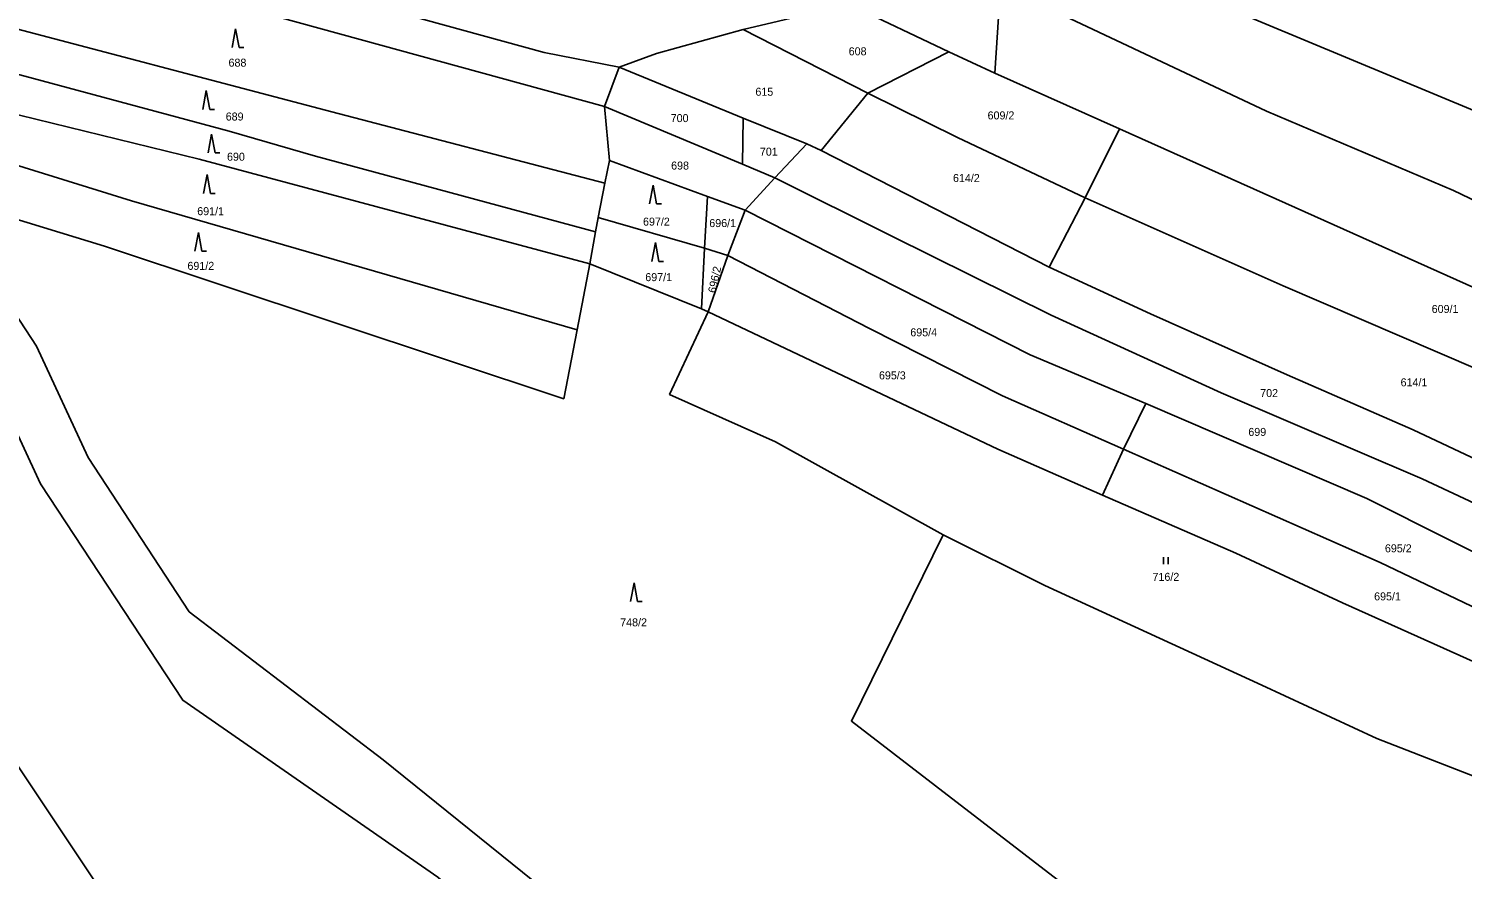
# Model space of a CAD drawing. Extents: x -7483133 to -743907, y -11317770 to -1129777.
# Drawn here: x -748843.6 to -748539, y -1131175.9 to -1130997.2 of the extents above; entities that cross this region are included whole.
import ezdxf

# ---------------------------------------------------------------- set-up
doc = ezdxf.new("R2010")
doc.units = 0
for name, color, linetype in [('Hranice parcel', 7, 'Continuous'), ('Parcelní čísla', 7, 'Continuous'), ('Značky kultur', 7, 'Continuous')]:
    doc.layers.add(name, color=color, linetype=linetype)

msp = doc.modelspace()

# ---------------------------------------------------------------- linework, layer by layer
at = {"layer": 'Hranice parcel'}
for p, q in [((-748638.28, -1131006.71), (-748637.1, -1130988.07)), ((-748669.28, -1130992.07), (-748691.81, -1130997.44)), ((-748669.28, -1130992.07), (-748648.09, -1131002.15)), ((-748691.81, -1130997.44), (-748665.29, -1131010.97)), ((-748665.29, -1131010.97), (-748648.09, -1131002.15)), ((-748648.09, -1131002.15), (-748638.28, -1131006.71)), ((-748721.27, -1131013.77), (-748718.11, -1131005.41)), ((-748718.11, -1131005.41), (-748691.78, -1131016.23)), ((-748638.28, -1131006.71), (-748611.82, -1131018.52)), ((-748665.29, -1131010.97), (-748675.21, -1131023.11)), ((-748691.89, -1131026.01), (-748721.27, -1131013.77)), ((-748720.21, -1131025.25), (-748721.27, -1131013.77)), ((-748691.89, -1131026.01), (-748691.78, -1131016.23)), ((-748691.78, -1131016.23), (-748678.26, -1131021.72)), ((-748611.82, -1131018.52), (-748619.14, -1131033.17)), ((-748685.08, -1131028.93), (-748678.26, -1131021.72)), ((-748678.26, -1131021.72), (-748675.21, -1131023.11)), ((-748675.21, -1131023.11), (-748626.79, -1131047.92)), ((-748721.16, -1131030.03), (-748720.21, -1131025.25)), ((-748699.34, -1131032.91), (-748720.21, -1131025.25)), ((-748685.08, -1131028.93), (-748691.89, -1131026.01)), ((-748722.61, -1131037.34), (-748721.16, -1131030.03)), ((-748691.34, -1131035.8), (-748685.08, -1131028.93)), ((-748699.34, -1131032.91), (-748700.01, -1131043.9)), ((-748691.34, -1131035.8), (-748699.34, -1131032.91)), ((-748619.14, -1131033.17), (-748626.79, -1131047.92)), ((-748691.34, -1131035.8), (-748695.07, -1131045.45)), ((-748723.16, -1131040.37), (-748722.61, -1131037.34)), ((-748700.01, -1131043.9), (-748722.61, -1131037.34)), ((-748724.39, -1131047.18), (-748723.16, -1131040.37)), ((-748700.01, -1131043.9), (-748700.66, -1131056.76)), ((-748700.01, -1131043.9), (-748695.07, -1131045.45)), ((-748695.07, -1131045.45), (-748699.23, -1131057.41)), ((-748724.39, -1131047.18), (-748727.08, -1131061.25)), ((-748700.66, -1131056.76), (-748724.39, -1131047.18)), ((-748699.23, -1131057.41), (-748700.66, -1131056.76)), ((-748606.26, -1131076.91), (-748610.96, -1131086.6)), ((-748610.96, -1131086.6), (-748615.45, -1131096.38))]:
    msp.add_line(p, q, dxfattribs=at)
for points in [[(-748718.11, -1131005.41), (-748734.03, -1131002.28), (-748798.34, -1130984.6), (-748831.06, -1130975.19), (-748876.9, -1130971.17)], [(-748876.9, -1130971.17), (-748808.26, -1130989.85), (-748721.27, -1131013.77)], [(-748433.86, -1131062.5), (-748469.72, -1131045.54), (-748503.59, -1131029.98), (-748535.57, -1131015.06), (-748590.35, -1130992.22), (-748617.7, -1130976.74)], [(-748883.92, -1130988.13), (-748855.69, -1130994.76), (-748779.2, -1131014.91), (-748721.16, -1131030.03)], [(-748637.1, -1130988.07), (-748580.62, -1131014.77), (-748540.84, -1131031.61), (-748501.83, -1131050.32), (-748475.33, -1131062.6), (-748443.88, -1131076.03)], [(-748887.11, -1130995.84), (-748800.99, -1131019), (-748782.66, -1131024.35), (-748723.16, -1131040.37)], [(-748691.81, -1130997.44), (-748710.23, -1131002.5), (-748718.11, -1131005.41)], [(-748890.71, -1131004.53), (-748807.39, -1131024.98), (-748724.39, -1131047.18)], [(-748665.29, -1131010.97), (-748646.27, -1131020.35), (-748619.14, -1131033.17)], [(-748887.67, -1131014.39), (-748859.22, -1131022.19), (-748821.78, -1131033.78), (-748727.08, -1131061.25)], [(-748611.82, -1131018.52), (-748576.55, -1131034.33), (-748532.02, -1131054.31), (-748497.74, -1131070.23), (-748452.21, -1131091.2)], [(-748392.16, -1131506.55), (-748408.97, -1131492.45), (-748455.93, -1131466.65), (-748484.5, -1131445.39), (-748502.39, -1131429.25), (-748511.24, -1131427.32), (-748518.9, -1131418.34), (-748522.93, -1131412.38), (-748534.82, -1131400.07), (-748560.04, -1131371.4), (-748567.63, -1131359.17), (-748618.14, -1131307.59), (-748670.88, -1131247.89), (-748697.81, -1131219.81), (-748711.66, -1131216.37), (-748756.69, -1131177.5), (-748810.83, -1131139.93), (-748841.05, -1131093.93), (-748849.27, -1131076.16), (-748875.35, -1131042.49), (-748884.41, -1131032.45), (-748897.97, -1131021.96), (-748903.36, -1131031.29)], [(-748474.34, -1131130), (-748517.39, -1131106.95), (-748547.53, -1131092.9), (-748590.2, -1131074.61), (-748626.34, -1131058.09), (-748660.21, -1131041.32), (-748685.08, -1131028.93)], [(-748903.36, -1131031.29), (-748905.89, -1131053.47), (-748901.45, -1131069.76), (-748894.6, -1131097.89), (-748881.04, -1131121.08), (-748873.58, -1131134.34), (-748846.57, -1131152.8), (-748823.65, -1131187.26), (-748755.15, -1131237.08), (-748782.58, -1131345.17), (-748793.36, -1131398.73), (-748812.12, -1131488.8), (-748821.02, -1131580.29), (-748829.28, -1131664.88)], [(-748727.08, -1131061.25), (-748729.9, -1131075.88), (-748827.51, -1131043.45), (-748862.93, -1131032.61)], [(-748862.93, -1131032.61), (-748841.96, -1131064.7), (-748830.94, -1131088.32), (-748809.47, -1131121.13), (-748768.27, -1131152.58), (-748729.51, -1131183.85), (-748683.15, -1131218.97), (-748628.13, -1131281.36), (-748623.2, -1131281.94), (-748602.24, -1131308.39), (-748580.92, -1131332.73), (-748557.75, -1131353.82), (-748544.86, -1131363.16), (-748538.91, -1131375.03), (-748525.17, -1131390.76), (-748504.57, -1131408.29), (-748496.26, -1131416.91), (-748493.37, -1131423.24), (-748472.53, -1131441.85), (-748441.17, -1131464.36)], [(-748619.14, -1131033.17), (-748577.08, -1131051.86), (-748535.69, -1131069.64), (-748460.58, -1131106.38)], [(-748606.26, -1131076.91), (-748630.79, -1131066.52), (-748691.34, -1131035.8)], [(-748610.96, -1131086.6), (-748636.68, -1131075.28), (-748664.94, -1131060.97), (-748695.07, -1131045.45)], [(-748626.79, -1131047.92), (-748605.21, -1131057.83), (-748576.19, -1131070.76), (-748549.44, -1131082.45), (-748510.22, -1131100.96), (-748469.85, -1131122.34)], [(-748699.23, -1131057.41), (-748707.43, -1131074.93), (-748684.92, -1131085.04), (-748649.3, -1131104.79)], [(-748615.45, -1131096.38), (-748637.66, -1131086.57), (-748699.23, -1131057.41)], [(-748484.95, -1131136.78), (-748524.02, -1131114.8), (-748559.26, -1131097.09), (-748606.26, -1131076.91)], [(-748489.31, -1131143.89), (-748527.26, -1131124.6), (-748556.46, -1131110.63), (-748610.96, -1131086.6)], [(-748502.01, -1131149.16), (-748525.66, -1131136.67), (-748564.41, -1131119.26), (-748587.13, -1131108.7), (-748615.45, -1131096.38)], [(-748441.17, -1131464.36), (-748441.27, -1131454.86), (-748468.06, -1131411.28), (-748480.68, -1131390.05), (-748513.08, -1131337.18), (-748535.65, -1131293.82), (-748524.03, -1131286.83), (-748537.13, -1131261.56), (-748549.98, -1131235.81), (-748668.77, -1131144.37), (-748649.3, -1131104.79)], [(-748649.3, -1131104.79), (-748627.72, -1131115.56), (-748581.58, -1131136.72), (-748557.17, -1131148.05), (-748507.63, -1131167.31)]]:
    msp.add_lwpolyline(points, dxfattribs=at)
at = {"layer": 'Značky kultur'}
for p, q in [((-748799.63, -1130997.26), (-748800.38, -1131001.26)), ((-748798.88, -1131001.26), (-748799.63, -1130997.26)), ((-748798.88, -1131001.26), (-748797.88, -1131001.26)), ((-748805.87, -1131010.37), (-748806.62, -1131014.37)), ((-748805.12, -1131014.37), (-748805.87, -1131010.37)), ((-748805.12, -1131014.37), (-748804.12, -1131014.37)), ((-748804.73, -1131019.62), (-748805.48, -1131023.62)), ((-748803.98, -1131023.62), (-748804.73, -1131019.62)), ((-748803.98, -1131023.62), (-748802.98, -1131023.62)), ((-748805.7, -1131028.22), (-748806.45, -1131032.22)), ((-748804.95, -1131032.22), (-748805.7, -1131028.22)), ((-748804.95, -1131032.22), (-748803.95, -1131032.22)), ((-748710.92, -1131030.46), (-748711.67, -1131034.46)), ((-748710.17, -1131034.46), (-748710.92, -1131030.46)), ((-748710.17, -1131034.46), (-748709.17, -1131034.46)), ((-748807.54, -1131040.51), (-748808.29, -1131044.51)), ((-748806.79, -1131044.51), (-748807.54, -1131040.51)), ((-748806.79, -1131044.51), (-748805.79, -1131044.51)), ((-748710.43, -1131042.69), (-748711.18, -1131046.69)), ((-748709.68, -1131046.69), (-748710.43, -1131042.69)), ((-748709.68, -1131046.69), (-748708.68, -1131046.69)), ((-748602.47, -1131111.01), (-748602.47, -1131109.51)), ((-748601.47, -1131111.01), (-748601.47, -1131109.51)), ((-748714.97, -1131114.97), (-748715.72, -1131118.97)), ((-748714.22, -1131118.97), (-748714.97, -1131114.97)), ((-748714.22, -1131118.97), (-748713.22, -1131118.97))]:
    msp.add_line(p, q, dxfattribs=at)

# ---------------------------------------------------------------- texts
at = {"layer": 'Parcelní čísla'}
for s, p in [('608', (-748669.36, -1131002.89)), ('688', (-748801.13, -1131005.3)), ('615', (-748689.18, -1131011.48)), ('689', (-748801.73, -1131016.75)), ('609/2', (-748639.85, -1131016.51)), ('700', (-748707.18, -1131017.08)), ('690', (-748801.45, -1131025.29)), ('701', (-748688.23, -1131024.21)), ('698', (-748707.09, -1131027.17)), ('614/2', (-748647.2, -1131029.82)), ('691/1', (-748807.78, -1131036.86)), ('697/2', (-748713.06, -1131039.08)), ('696/1', (-748698.98, -1131039.39)), ('691/2', (-748809.86, -1131048.48)), ('697/1', (-748712.58, -1131050.88)), ('609/1', (-748545.49, -1131057.64)), ('695/4', (-748656.27, -1131062.6)), ('695/3', (-748662.93, -1131071.75)), ('614/1', (-748552.1, -1131073.23)), ('702', (-748581.93, -1131075.51)), ('699', (-748584.45, -1131083.77)), ('695/2', (-748555.43, -1131108.5)), ('716/2', (-748604.81, -1131114.56)), ('695/1', (-748557.72, -1131118.71)), ('748/2', (-748717.91, -1131124.23))]:
    msp.add_text(s, height=1.7, dxfattribs=at).set_placement(p)
msp.add_text('696/2', height=1.7, rotation=78, dxfattribs=at).set_placement((-748697.61, -1131053.51))

doc.saveas('drawing.dxf')
